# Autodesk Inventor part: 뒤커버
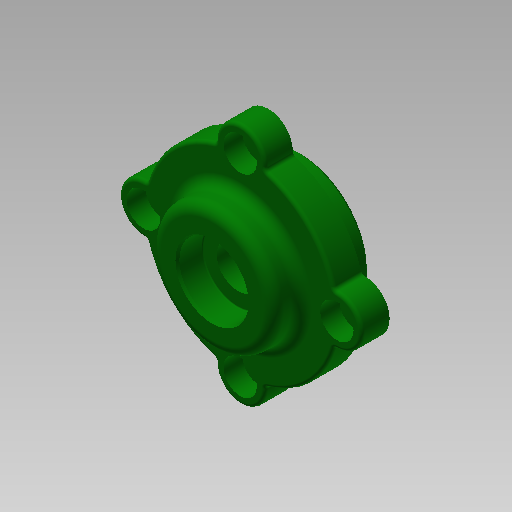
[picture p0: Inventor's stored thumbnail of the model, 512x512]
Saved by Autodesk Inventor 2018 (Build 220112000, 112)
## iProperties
Created: 2016-05
Part Number: 뒤커버
Document SubType Name: Modeling
Designer: mduedu
Density: 2.71 g/cm^3
Material: 알루미늄 6061
Appearance: 진녹색
Author: mduedu
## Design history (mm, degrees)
sketch "스케치1"
  geometry: C1 r 20 at (0, 0); C2 r 27.5 at (0, 0); 1 further point
  constraints: 2 centre point, 2 coincident
  dimensions: "d33" = 55 diameter of C2; "d34" = 40 diameter of C1
extrude "돌출1" new body sketch "스케치1" distance "d0" = 8; taper "d1" = 0 deg
extrude "돌출2" join sketch "스케치1" distance "d2" = 8; taper "d3" = 0 deg; dims "d35" = 9, "d36" = 0
sketch "스케치6"
  geometry: C1 r 17.5 at (0, 0); 2 further points
  constraints: 2 coincident, 1 centre point
  dimensions: "d42" = 35 diameter of C1
extrude "돌출4" join sketch "스케치6" distance "d43" = 8; taper "d44" = 0 deg
sketch "스케치4"
  geometry: L1 (0, -9)-(0, 16); L2 (-15, -9)-(-15, 0); L3 (-15, 0)-(-10, 0); L4 (-10, 0)-(-10, 3); L5 (-10, 3)-(-6, 3); L6 (-6, 3)-(-6, 8.7); L7 (-6, 8.7)-(-10, 8.7); L8 (-10, 8.7)-(-10, 16); L9 (20, -9)-(-20, -9) reference; L10 (17.5, 16)-(-17.5, 16) reference; 1 further point
  constraints: 16 end point, 6 parallel, 3 point on line, 2 midpoint, 2 perpendicular, 1 vertical
  dimensions: "d15" = 30 diameter of L2 L1; "d16" = 20 diameter of L8 L1; "d18" = 9 distance of L2.start L2.end; "d19" = 3 distance of L3.end L4.end; "d20" = 20 diameter of L4 L1; "d21" = 12 diameter of L6 L1; "d45" = 7.3 distance of L7.end L8.end
revolve "회전1" sketch "스케치4" stored, may be unused: angle "d22" = 90 deg
fillet "모깎기2" dims "d23" = 3
fillet "모깎기3" dims "d24" = 0.3
chamfer "모따기2" distance "d46" = 1; stored, may be unused: second distance "d47" = 2, angle "d48" = 45 deg
sketch "스케치7"
  geometry: C1 r 7 at (0, 27.5); 2 further points
  constraints: 3 vertical alignment, 1 centre point, 2 other
  dimensions: "d54" = 14 diameter of C1
extrude "돌출5" join sketch "스케치7" stored distance "d55" = 10; taper "d56" = 0 deg
fillet "모깎기6" dims "d57" = 1
sketch "스케치10"
  geometry: C1 r 17.5 at (0, 0) reference; A1 r 27.5 centre (0, 0) between (26.395, 7.718) and (7.718, 26.395) reference; A2 r 1 centre (7.999, 27.355) between (6.999, 27.373) and (7.718, 26.395) reference; A3 r 7 centre (0, 27.5) between (6.999, 27.373) and (-6.999, 27.373) reference; A4 r 1 centre (-7.999, 27.355) between (-7.718, 26.395) and (-6.999, 27.373) reference; A5 r 27.5 centre (0, 0) between (-7.718, 26.395) and (-26.395, 7.718) reference; A6 r 1 centre (-27.355, 7.999) between (-27.373, 6.999) and (-26.395, 7.718) reference; A7 r 7 centre (-27.5, 0) between (-27.373, 6.999) and (-27.373, -6.999) reference; A8 r 1 centre (-27.355, -7.999) between (-26.395, -7.718) and (-27.373, -6.999) reference; A9 r 27.5 centre (0, 0) between (-26.395, -7.718) and (-7.718, -26.395) reference; A10 r 1 centre (-7.999, -27.355) between (-6.999, -27.373) and (-7.718, -26.395) reference; A11 r 7 centre (0, -27.5) between (-6.999, -27.373) and (6.999, -27.373) reference; A12 r 1 centre (7.999, -27.355) between (7.718, -26.395) and (6.999, -27.373) reference; A13 r 27.5 centre (0, 0) between (7.718, -26.395) and (26.395, -7.718) reference; A14 r 1 centre (27.355, -7.999) between (27.373, -6.999) and (26.395, -7.718) reference; A15 r 7 centre (27.5, 0) between (27.373, -6.999) and (27.373, 6.999) reference; A16 r 1 centre (27.355, 7.999) between (26.395, 7.718) and (27.373, 6.999) reference; 4 further points
  constraints: 3 coincident
hole "구멍3" sketch "스케치10" at (0, 27.5), (-27.5, 0), (0, -27.5), (27.5, 0) diameter "d81" = 5.5; stored, may be unused: countersink angle "d85" = 90 deg, drill point angle "d87" = 118 deg; dims "d82" = 6, "d83" = 9.5, "d84" = 5.4, "d86" = 8
fillet "모깎기7" dims "d61" = 1
fillet "모깎기8" dims "d88" = 3
chamfer "모따기3" distance "d76" = 0.7; stored, may be unused: second distance "d77" = 2, angle "d78" = 30 deg
node "솔리드1"
pattern_circular "원형 패턴1" dims angle "d59" = 360 deg
node "투영된 루프1"
